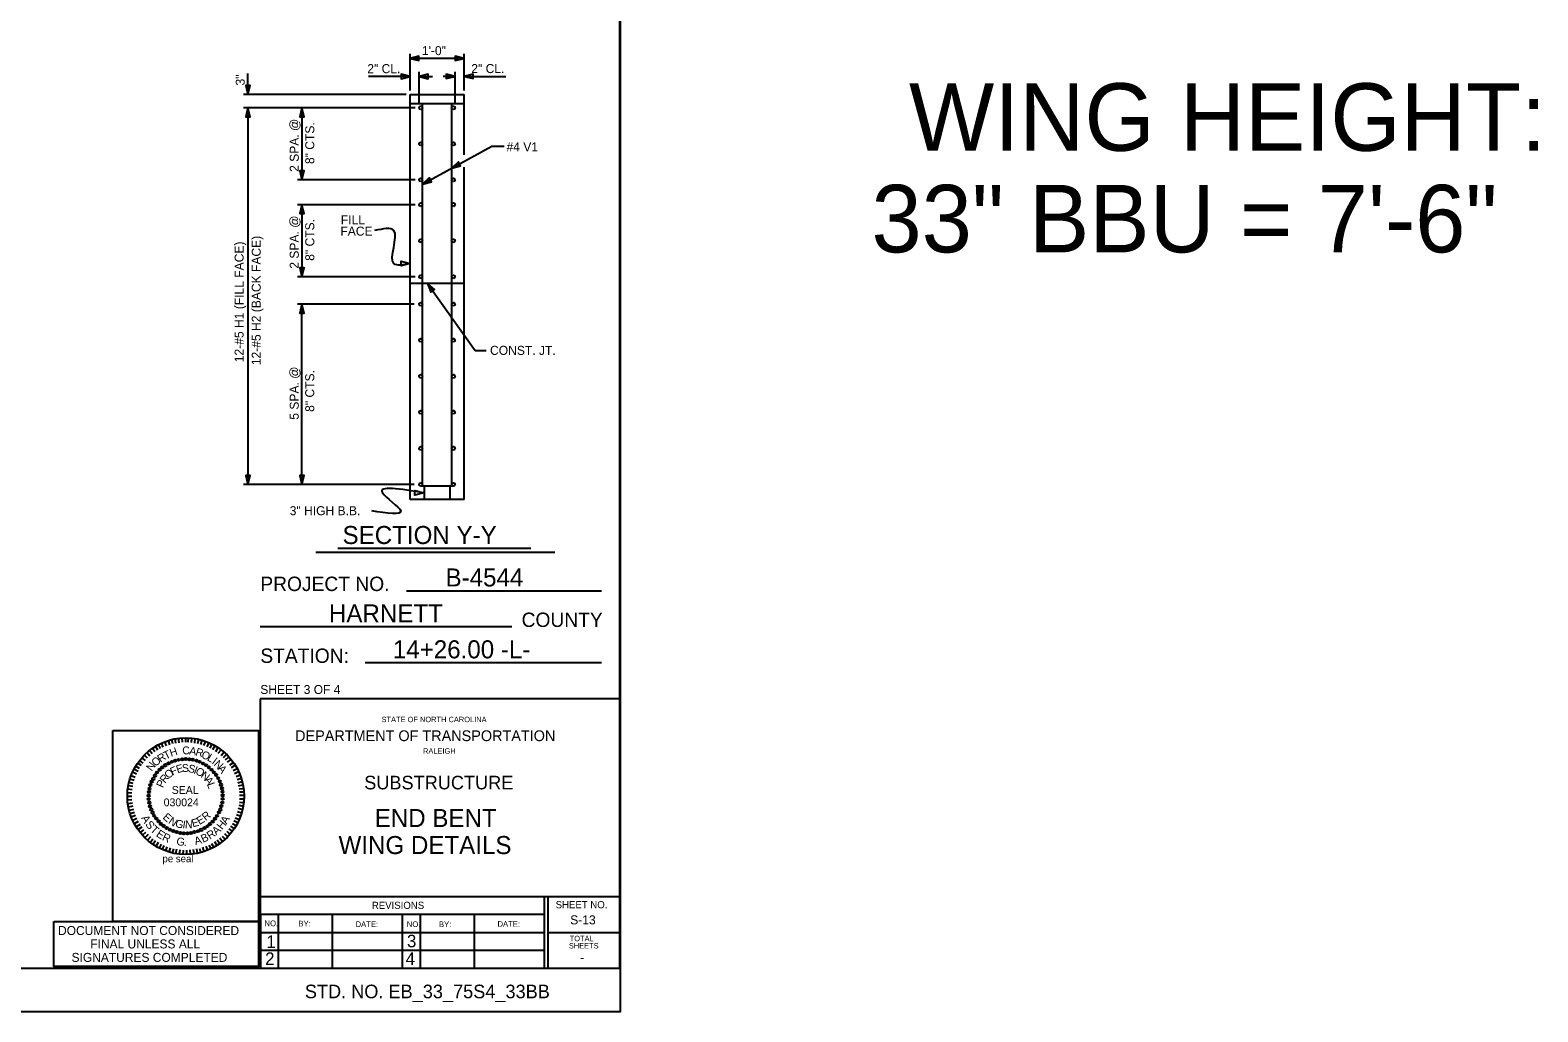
# Model space of a CAD drawing. Extents: x -41 to 191, y -168 to 6.
# Drawn here: x 33.05 to 60.96, y -98.82 to -80.65 of the extents above; entities that cross this region are included whole.
import ezdxf

# ---------------------------------------------------------------- set-up
doc = ezdxf.new("R2010")
doc.units = 0
for name, color, linetype in [('Arrowhead Terminators CELL', 7, 'Continuous'), ('Dimension Lines', 7, 'Continuous'), ('Mis Object Lines', 7, 'Continuous'), ('Mis Object Lines Hidden', 7, 'Continuous'), ('Peseal', 7, 'Continuous'), ('Plan Sheet CELL', 7, 'Continuous'), ('Plot Shape CELL', 7, 'Continuous'), ('Rebar Lines', 7, 'Continuous'), ('Sheet Sticker Exception Certification CELL', 7, 'Continuous'), ('Subtitle Text', 7, 'Continuous'), ('Text', 7, 'Continuous'), ('Title Text', 7, 'Continuous'), ('User Information Notes', 7, 'Continuous'), ('User Information Notes CELL', 7, 'Continuous')]:
    doc.layers.add(name, color=color, linetype=linetype)

msp = doc.modelspace()

# ---------------------------------------------------------------- linework, layer by layer
at = {"layer": 'Arrowhead Terminators CELL'}
for points in [[(40.084, -81.175), (40.25, -81.216), (40.25, -81.133)], [(41.084, -81.175), (40.918, -81.133), (40.918, -81.216)], [(40.084, -81.509), (39.918, -81.468), (39.918, -81.551)], [(40.251, -81.509), (40.417, -81.551), (40.417, -81.468)], [(40.918, -81.508), (40.751, -81.466), (40.751, -81.549)], [(41.084, -81.508), (41.25, -81.549), (41.25, -81.466)], [(37.084, -81.841), (37.126, -81.675), (37.043, -81.675)], [(37.084, -82.091), (37.043, -82.257), (37.126, -82.257)], [(38.084, -82.091), (38.043, -82.257), (38.126, -82.257)], [(40.855, -83.206), (41.021, -83.162), (40.981, -83.089)], [(38.084, -83.425), (38.126, -83.258), (38.043, -83.258)], [(40.314, -83.504), (40.479, -83.46), (40.439, -83.387)], [(38.084, -83.883), (38.043, -84.049), (38.126, -84.049)], [(38.084, -85.216), (38.126, -85.05), (38.043, -85.05)], [(40.084, -84.973), (39.918, -85.014), (39.918, -84.931)], [(40.408, -85.341), (40.47, -85.501), (40.538, -85.453)], [(38.084, -85.726), (38.043, -85.893), (38.126, -85.893)], [(37.084, -89.06), (37.126, -88.893), (37.043, -88.893)], [(38.084, -89.06), (38.126, -88.893), (38.043, -88.893)], [(40.338, -89.217), (40.172, -89.259), (40.172, -89.176)]]:
    msp.add_lwpolyline(points, close=True, dxfattribs=at)
at = {"layer": 'Dimension Lines'}
for p, q in [((40.084, -81.769), (40.084, -81.091)), ((41.084, -81.175), (40.084, -81.175)), ((41.084, -81.769), (41.084, -81.091)), ((37.084, -81.841), (37.084, -81.454)), ((40.251, -82.019), (40.251, -81.426)), ((40.918, -82.019), (40.918, -81.425)), ((40.084, -81.509), (39.314, -81.509)), ((40.251, -81.509), (40.497, -81.509)), ((40.918, -81.508), (40.695, -81.508)), ((41.084, -81.508), (41.859, -81.508)), ((40.012, -81.841), (37.001, -81.841)), ((40.18, -82.091), (37.001, -82.091)), ((37.084, -82.091), (37.084, -89.06)), ((38.084, -82.091), (38.084, -83.425)), ((40.314, -83.504), (41.598, -82.797)), ((41.598, -82.797), (41.824, -82.797)), ((40.18, -83.425), (38.001, -83.425)), ((40.18, -83.883), (38.001, -83.883)), ((38.084, -83.883), (38.084, -85.216)), ((40.18, -85.216), (38.001, -85.216)), ((40.408, -85.341), (41.29, -86.581)), ((40.16, -85.726), (38.001, -85.726)), ((38.084, -89.06), (38.084, -85.726)), ((41.29, -86.581), (41.494, -86.581)), ((40.16, -89.06), (37.001, -89.06))]:
    msp.add_line(p, q, dxfattribs=at)
for points in [[(40.084, -84.973), (39.787, -84.973), (39.787, -84.363), (39.429, -84.363)], [(40.338, -89.217), (39.572, -89.217), (39.911, -89.55), (39.374, -89.55)]]:
    msp.add_spline(points, degree=3, dxfattribs=at)
at = {"layer": 'Mis Object Lines'}
for p, q in [((40.084, -89.341), (40.084, -81.841)), ((40.084, -81.841), (41.084, -81.841)), ((41.084, -82.962), (41.084, -81.841)), ((41.084, -89.341), (41.084, -83.188)), ((41.084, -89.341), (40.084, -89.341))]:
    msp.add_line(p, q, dxfattribs=at)
at = {"layer": 'Mis Object Lines Hidden'}
msp.add_line((41.084, -85.341), (40.084, -85.341), dxfattribs=at)
at = {"layer": 'Peseal'}
for p, q in [((35.808, -93.844), (35.798, -93.761)), ((35.87, -93.833), (35.865, -93.75)), ((35.933, -93.833), (35.933, -93.75)), ((35.979, -93.833), (35.985, -93.75)), ((36.037, -93.839), (36.047, -93.756)), ((35.268, -94.088), (35.216, -94.026)), ((35.314, -94.046), (35.262, -93.984)), ((35.361, -94.01), (35.314, -93.943)), ((35.413, -93.979), (35.372, -93.906)), ((35.465, -93.948), (35.429, -93.875)), ((35.517, -93.922), (35.486, -93.849)), ((35.579, -93.901), (35.548, -93.823)), ((35.637, -93.88), (35.611, -93.797)), ((35.694, -93.865), (35.673, -93.782)), ((35.751, -93.849), (35.735, -93.766)), ((36.099, -93.849), (36.109, -93.766)), ((36.156, -93.859), (36.172, -93.776)), ((36.213, -93.875), (36.234, -93.792)), ((36.27, -93.891), (36.302, -93.813)), ((36.327, -93.917), (36.364, -93.839)), ((36.385, -93.943), (36.421, -93.865)), ((36.437, -93.969), (36.478, -93.896)), ((36.489, -94.005), (36.535, -93.932)), ((36.535, -94.036), (36.587, -93.974)), ((36.587, -94.078), (36.639, -94.015)), ((35.075, -94.317), (35.003, -94.275)), ((35.112, -94.265), (35.039, -94.218)), ((35.143, -94.218), (35.081, -94.171)), ((35.185, -94.171), (35.122, -94.119)), ((35.226, -94.13), (35.164, -94.067)), ((36.629, -94.114), (36.686, -94.057)), ((36.67, -94.161), (36.733, -94.104)), ((36.707, -94.202), (36.774, -94.15)), ((36.748, -94.254), (36.816, -94.208)), ((36.779, -94.301), (36.847, -94.259)), ((36.811, -94.353), (36.883, -94.317)), ((34.961, -94.597), (34.883, -94.576)), ((34.977, -94.54), (34.899, -94.514)), ((34.997, -94.483), (34.92, -94.452)), ((35.023, -94.426), (34.946, -94.389)), ((35.049, -94.374), (34.972, -94.332)), ((36.837, -94.41), (36.909, -94.374)), ((36.863, -94.467), (36.941, -94.436)), ((36.883, -94.524), (36.961, -94.498)), ((36.899, -94.582), (36.977, -94.561)), ((34.935, -94.774), (34.852, -94.769)), ((34.935, -94.836), (34.852, -94.836)), ((34.94, -94.711), (34.862, -94.701)), ((34.951, -94.654), (34.868, -94.639)), ((36.909, -94.639), (36.992, -94.623)), ((36.92, -94.696), (37.003, -94.686)), ((36.925, -94.753), (37.008, -94.748)), ((36.93, -94.815), (37.013, -94.815)), ((36.93, -94.878), (37.013, -94.883)), ((34.935, -94.899), (34.852, -94.904)), ((34.946, -94.961), (34.862, -94.971)), ((34.951, -95.018), (34.873, -95.034)), ((34.966, -95.075), (34.883, -95.096)), ((34.982, -95.132), (34.904, -95.158)), ((36.889, -95.112), (36.972, -95.138)), ((36.904, -95.054), (36.987, -95.075)), ((36.915, -94.997), (36.998, -95.013)), ((36.925, -94.94), (37.008, -94.95)), ((35.003, -95.189), (34.925, -95.221)), ((35.029, -95.247), (34.951, -95.283)), ((35.055, -95.299), (34.977, -95.34)), ((35.086, -95.356), (35.013, -95.397)), ((35.117, -95.402), (35.049, -95.449)), ((36.728, -95.434), (36.795, -95.486)), ((36.759, -95.387), (36.831, -95.434)), ((36.795, -95.335), (36.868, -95.376)), ((36.821, -95.283), (36.899, -95.319)), ((36.847, -95.231), (36.925, -95.262)), ((36.873, -95.169), (36.951, -95.2)), ((35.153, -95.454), (35.086, -95.506)), ((35.19, -95.501), (35.133, -95.553)), ((35.236, -95.543), (35.174, -95.605)), ((35.278, -95.584), (35.226, -95.647)), ((35.325, -95.626), (35.278, -95.688)), ((35.372, -95.657), (35.325, -95.725)), ((35.424, -95.688), (35.382, -95.761)), ((36.411, -95.704), (36.452, -95.782)), ((36.463, -95.673), (36.509, -95.745)), ((36.515, -95.641), (36.561, -95.709)), ((36.561, -95.605), (36.613, -95.673)), ((36.608, -95.569), (36.66, -95.626)), ((36.65, -95.522), (36.712, -95.584)), ((36.691, -95.48), (36.754, -95.538)), ((35.475, -95.719), (35.439, -95.792)), ((35.527, -95.745), (35.496, -95.818)), ((35.585, -95.766), (35.559, -95.844)), ((35.647, -95.787), (35.621, -95.865)), ((35.704, -95.803), (35.683, -95.88)), ((35.761, -95.813), (35.746, -95.896)), ((35.824, -95.823), (35.813, -95.906)), ((35.886, -95.828), (35.881, -95.912)), ((35.948, -95.828), (35.948, -95.912)), ((36.011, -95.823), (36.016, -95.906)), ((36.073, -95.818), (36.083, -95.901)), ((36.13, -95.808), (36.146, -95.891)), ((36.187, -95.797), (36.208, -95.875)), ((36.244, -95.777), (36.27, -95.86)), ((36.302, -95.756), (36.333, -95.834)), ((36.359, -95.735), (36.395, -95.808))]:
    msp.add_line(p, q, dxfattribs=at)
for centre, radius in [((35.449, -94.343), 0.022), ((35.499, -94.298), 0.0223), ((35.556, -94.257), 0.0223), ((35.616, -94.223), 0.0232), ((35.675, -94.195), 0.0198), ((35.735, -94.174), 0.0189), ((35.8, -94.158), 0.0184), ((35.868, -94.15), 0.0209), ((35.933, -94.145), 0.0208), ((35.998, -94.15), 0.0209), ((36.063, -94.156), 0.0214), ((36.13, -94.174), 0.0189), ((36.19, -94.195), 0.0198), ((36.25, -94.226), 0.0209), ((36.307, -94.257), 0.0209), ((36.361, -94.296), 0.0203), ((36.413, -94.343), 0.0203), ((35.301, -94.563), 0.0198), ((35.333, -94.509), 0.0239), ((35.364, -94.449), 0.0223), ((35.4, -94.392), 0.0184), ((36.457, -94.392), 0.0203), ((36.496, -94.441), 0.0209), ((36.533, -94.498), 0.0209), ((36.564, -94.558), 0.0198), ((36.587, -94.621), 0.0222), ((35.247, -94.821), 0.0208), ((35.247, -94.886), 0.0209), ((35.252, -94.756), 0.0209), ((35.262, -94.691), 0.0214), ((35.278, -94.626), 0.0222), ((36.603, -94.686), 0.0214), ((36.613, -94.75), 0.0209), ((36.618, -94.88), 0.0209), ((36.618, -94.815), 0.0208), ((35.257, -94.953), 0.0209), ((35.273, -95.018), 0.0214), ((35.294, -95.078), 0.0222), ((35.32, -95.138), 0.0232), ((36.548, -95.132), 0.0209), ((36.572, -95.078), 0.0222), ((36.592, -95.013), 0.0214), ((36.608, -94.948), 0.0209), ((35.348, -95.195), 0.0209), ((35.387, -95.244), 0.0203), ((35.429, -95.299), 0.022), ((35.475, -95.345), 0.022), ((35.525, -95.384), 0.0223), ((35.579, -95.421), 0.0209), ((35.639, -95.452), 0.0198), ((36.218, -95.454), 0.0232), ((36.281, -95.421), 0.0209), ((36.335, -95.387), 0.0203), ((36.382, -95.345), 0.0203), ((36.431, -95.301), 0.0203), ((36.476, -95.249), 0.0223), ((36.512, -95.195), 0.0209), ((35.701, -95.475), 0.0222), ((35.766, -95.496), 0.0214), ((35.831, -95.512), 0.0209), ((35.896, -95.517), 0.0208), ((35.964, -95.517), 0.0208), ((36.029, -95.512), 0.0209), ((36.094, -95.496), 0.0214), ((36.159, -95.478), 0.0198)]:
    msp.add_circle(centre, radius, dxfattribs=at)
at = {"layer": 'Plan Sheet CELL'}
for p, q in [((43.962, -70.087), (43.962, -98.017)), ((43.63, -91.034), (40.016, -91.034)), ((41.967, -91.699), (37.313, -91.699)), ((43.63, -92.364), (39.255, -92.364)), ((43.962, -93.029), (37.313, -93.029)), ((37.313, -93.029), (37.313, -98.017)), ((37.313, -96.686), (43.962, -96.686)), ((42.566, -96.686), (42.566, -98.017)), ((42.633, -96.686), (42.633, -98.017)), ((37.313, -97.018), (42.569, -97.018)), ((37.317, -97.018), (37.317, -98.017)), ((37.645, -97.018), (37.645, -98.017)), ((38.642, -97.024), (38.642, -98.022)), ((39.94, -97.018), (39.94, -98.025)), ((40.273, -97.018), (40.273, -98.018)), ((41.271, -97.018), (41.271, -98.018)), ((37.313, -97.352), (42.58, -97.352)), ((42.633, -97.352), (43.951, -97.352)), ((37.313, -97.684), (42.569, -97.684)), ((1.402, -98.017), (43.962, -98.017)), ((43.974, -98.823), (43.974, -98.823))]:
    msp.add_line(p, q, dxfattribs=at)
at = {"layer": 'Plot Shape CELL'}
msp.add_lwpolyline([(0, -69.563), (43.974, -69.563), (43.974, -98.823), (0, -98.823)], close=True, dxfattribs=at)
at = {"layer": 'Rebar Lines'}
for p, q in [((40.314, -89.091), (40.314, -82.008)), ((40.855, -89.091), (40.855, -82.008)), ((40.886, -89.091), (40.282, -89.091)), ((40.346, -89.091), (40.346, -89.341)), ((40.821, -89.091), (40.821, -89.341))]:
    msp.add_line(p, q, dxfattribs=at)
for centre in [(40.282, -82.091), (40.886, -82.091), (40.282, -82.758), (40.886, -82.758), (40.282, -83.425), (40.886, -83.425), (40.282, -83.883), (40.886, -83.883), (40.282, -84.55), (40.886, -84.55), (40.282, -85.216), (40.886, -85.216), (40.282, -85.726), (40.886, -85.726), (40.282, -86.393), (40.886, -86.393), (40.282, -87.06), (40.886, -87.06), (40.282, -87.726), (40.886, -87.726), (40.282, -88.393), (40.886, -88.393), (40.282, -89.06), (40.886, -89.06)]:
    msp.add_ellipse(centre, major_axis=(0, -0.0313), ratio=0.99999, dxfattribs=at)
at = {"layer": 'Sheet Sticker Exception Certification CELL'}
msp.add_lwpolyline([(33.491, -97.15), (37.279, -97.15), (37.279, -97.983), (33.491, -97.983)], close=True, dxfattribs=at)
at = {"layer": 'Title Text'}
for p, q in [((38.342, -90.313), (42.764, -90.313)), ((38.745, -90.24), (42.319, -90.24))]:
    msp.add_line(p, q, dxfattribs=at)
at = {"layer": 'User Information Notes'}
msp.add_line((35.933, -94.831), (35.933, -94.831), dxfattribs=at)
at = {"layer": 'User Information Notes CELL'}
for p, q in [((40.084, -82.008), (41.084, -82.008)), ((35.933, -94.831), (35.933, -94.831))]:
    msp.add_line(p, q, dxfattribs=at)
msp.add_lwpolyline([(34.586, -93.617), (37.279, -93.617), (37.279, -97.15), (34.586, -97.15)], close=True, dxfattribs=at)
msp.add_circle((35.933, -94.831), 1.081, dxfattribs=at)

# ---------------------------------------------------------------- texts
at = {"layer": 'Peseal'}
for s, height, rotation, p in [('R', 0.145, 32.9699, (35.465, -94.213)), ('T', 0.145, 25.943, (35.564, -94.156)), ('H', 0.145, 18.9162, (35.662, -94.104)), ('C', 0.145, 4.8625, (35.875, -94.062)), ('A', 0.145, 350.8088, (35.99, -94.057)), ('R', 0.145, 343.7819, (36.104, -94.072)), ('O', 0.145, 336.7551, (36.208, -94.114)), ('L', 0.145, 329.7282, (36.317, -94.161)), ('N', 0.145, 54.0504, (35.304, -94.379)), ('O', 0.145, 39.9967, (35.372, -94.291)), ('F', 0.145, 26.4777, (35.688, -94.452)), ('E', 0.145, 18.4448, (35.782, -94.41)), ('S', 0.145, 2.3789, (35.865, -94.384)), ('S', 0.145, 346.313, (35.964, -94.379)), ('I', 0.145, 338.28, (36.068, -94.405)), ('O', 0.145, 330.2471, (36.099, -94.41)), ('I', 0.145, 322.7014, (36.405, -94.218)), ('N', 0.145, 315.6745, (36.442, -94.249)), ('A', 0.145, 308.6477, (36.515, -94.327)), ('P', 0.145, 66.6424, (35.512, -94.686)), ('R', 0.145, 50.5765, (35.548, -94.602)), ('O', 0.145, 42.5436, (35.616, -94.519)), ('N', 0.145, 322.2141, (36.198, -94.472)), ('A', 0.145, 306.1483, (36.27, -94.535)), ('L', 0.145, 290.0824, (36.322, -94.608)), ('E', 0.145, 318.5179, (35.496, -95.236)), ('R', 0.145, 38.6997, (36.302, -95.293)), ('A', 0.148, 300.3993, (35.102, -95.234)), ('S', 0.148, 309.4349, (35.175, -95.36)), ('T', 0.148, 318.1096, (35.264, -95.468)), ('N', 0.145, 326.5361, (35.6, -95.325)), ('G', 0.145, 342.5725, (35.725, -95.392)), ('I', 0.145, 350.5906, (35.865, -95.423)), ('N', 0.145, 358.6088, (35.917, -95.423)), ('E', 0.145, 14.6452, (36.063, -95.408)), ('E', 0.145, 30.6815, (36.187, -95.366)), ('A', 0.148, 42.3241, (36.499, -95.561)), ('H', 0.148, 51.3597, (36.606, -95.463)), ('A', 0.148, 59.6007, (36.69, -95.36)), ('E', 0.148, 327.1453, (35.372, -95.565)), ('R', 0.148, 335.458, (35.484, -95.638)), ('G', 0.148, 353.3858, (35.754, -95.737)), ('A', 0.148, 15.7955, (36.113, -95.737)), ('B', 0.148, 24.8312, (36.253, -95.697)), ('R', 0.148, 33.5776, (36.381, -95.638)), ('.', 0.148, 2.1323, (35.894, -95.754))]:
    msp.add_text(s, height=height, rotation=rotation, dxfattribs=at).set_placement(p)
for s, p in [('030024', (35.524, -95.018)), ('SEAL', (35.673, -94.789))]:
    msp.add_text(s, height=0.1455, dxfattribs=at).set_placement(p)
at = {"layer": 'Plan Sheet CELL'}
for s, height, p in [('PROJECT NO.', 0.266, (37.313, -91.034)), ('COUNTY', 0.266, (42.149, -91.699)), ('STATION:', 0.266, (37.313, -92.364)), ('SHEET 3 OF 4', 0.16625, (37.313, -92.94)), ('STATE OF NORTH CAROLINA', 0.09974, (39.557, -93.461)), ('DEPARTMENT OF TRANSPORTATION', 0.19949, (37.957, -93.812)), ('RALEIGH', 0.0997, (40.325, -94.045)), ('REVISIONS', 0.133, (39.377, -96.918)), ('SHEET NO.', 0.133, (42.779, -96.906)), ('NO.', 0.106, (37.391, -97.238)), ('BY:', 0.106, (38.019, -97.243)), ('DATE:', 0.106, (39.076, -97.254)), ('NO.', 0.106, (40.025, -97.254)), ('3', 0.233, (40.027, -97.628)), ('BY:', 0.106, (40.619, -97.255)), ('DATE:', 0.106, (41.703, -97.249)), ('1', 0.233, (37.426, -97.639)), ('SHEETS', 0.0997, (43.024, -97.65)), ('TOTAL', 0.0997, (43.04, -97.515)), ('2', 0.233, (37.402, -97.955)), ('4', 0.233, (40.003, -97.955))]:
    msp.add_text(s, height=height, dxfattribs=at).set_placement(p)
at = {"layer": 'Sheet Sticker Exception Certification CELL'}
for s, p in [('DOCUMENT NOT CONSIDERED', (33.569, -97.401)), ('FINAL UNLESS ALL', (34.165, -97.649)), ('SIGNATURES COMPLETED', (33.819, -97.898))]:
    msp.add_text(s, height=0.16588, dxfattribs=at).set_placement(p)
at = {"layer": 'Subtitle Text'}
for s, p in [('SUBSTRUCTURE', (39.236, -94.705)), ('STD. NO. EB_33_75S4_33BB', (38.137, -98.571))]:
    msp.add_text(s, height=0.25108, dxfattribs=at).set_placement(p)
at = {"layer": 'Text'}
for s, rotation, p in [('1\'-0"', 360, (40.304, -81.115)), ('3"', 90, (37.024, -81.677)), ('2" CL.', 360, (39.293, -81.449)), ('2" CL.', 360, (41.218, -81.447)), ('2 SPA. @', 90, (38.025, -83.276)), ('8" CTS.', 90, (38.312, -83.131)), ('#4 V1', 360, (41.87, -82.897)), ('2 SPA. @', 90, (38.025, -85.068)), ('8" CTS.', 90, (38.312, -84.922)), ('FILL', 360, (38.803, -84.247)), ('12-#5 H2 (BACK FACE)', 90, (37.321, -86.854)), ('FACE', 360, (38.795, -84.456)), ('12-#5 H1 (FILL FACE)', 90, (37.004, -86.799)), ('CONST. JT.', 360, (41.565, -86.663)), ('5 SPA. @', 90, (38.024, -87.863)), ('8" CTS.', 90, (38.311, -87.718))]:
    msp.add_text(s, height=0.167, rotation=rotation, dxfattribs=at).set_placement(p)
for s, height, p in [('WING HEIGHT:', 1.25, (49.319, -82.886)), ('33" BBU = 7\'-6"', 1.25, (48.625, -84.766)), ('3" HIGH B.B.', 0.167, (37.857, -89.631)), ('S-13', 0.167, (43.049, -97.204)), ('-', 0.167, (43.232, -97.901))]:
    msp.add_text(s, height=height, dxfattribs=at).set_placement(p)
at = {"layer": 'Title Text'}
for s, height, p in [('SECTION Y-Y', 0.33399, (38.835, -90.164)), ('B-4544', 0.334, (40.741, -90.95)), ('HARNETT', 0.334, (38.583, -91.615)), ('14+26.00 -L-', 0.334, (39.766, -92.28)), ('END BENT', 0.334, (39.43, -95.402)), ('WING DETAILS', 0.33399, (38.761, -95.903))]:
    msp.add_text(s, height=height, dxfattribs=at).set_placement(p)
at = {"layer": 'User Information Notes CELL'}
msp.add_text('pe seal', height=0.133, dxfattribs=at).set_placement((35.502, -96.054))

doc.saveas('drawing.dxf')
